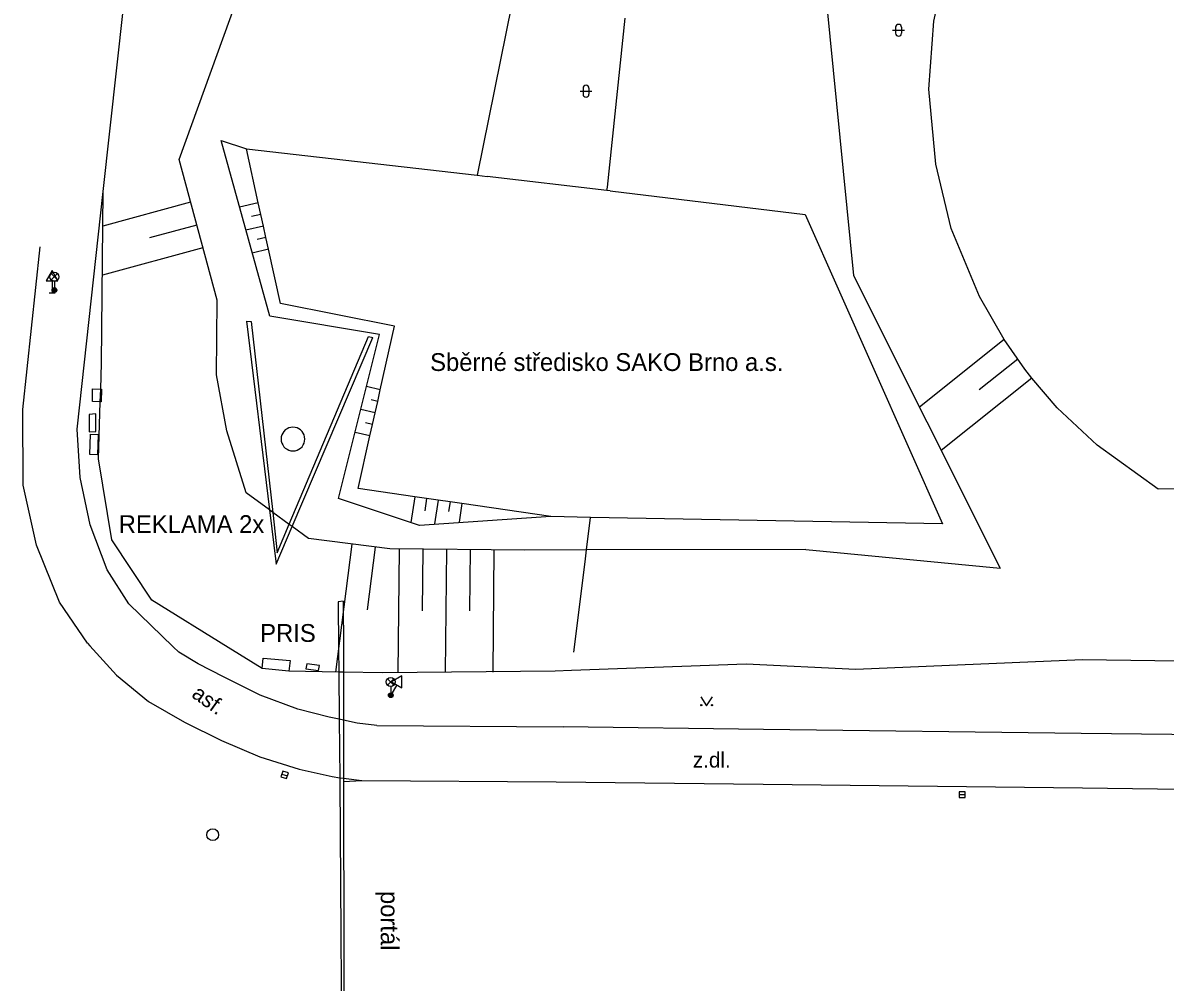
# Model space of a CAD drawing. Extents: x -602419 to -601554, y -1162937 to -1162362.
# Drawn here: x -602032.16 to -601984.03, y -1162718.74 to -1162678.29 of the extents above; entities that cross this region are included whole.
import ezdxf

# ---------------------------------------------------------------- set-up
doc = ezdxf.new("R2010")
doc.units = 0
doc.layers.add('Podklad', color=7, linetype='Continuous')

msp = doc.modelspace()

# ---------------------------------------------------------------- linework, layer by layer
at = {"layer": 'Podklad'}
for p, q in [((-601995.513, -1162678.608), (-601995.013, -1162678.608)), ((-601995.388, -1162678.483), (-601995.388, -1162678.733)), ((-601995.138, -1162678.483), (-601995.138, -1162678.733)), ((-602008.683, -1162681.178), (-602008.183, -1162681.178)), ((-602008.558, -1162681.053), (-602008.558, -1162681.303)), ((-602008.308, -1162681.053), (-602008.308, -1162681.303)), ((-602032.1599, -1162694.59), (-602031.43, -1162687.73)), ((-602030.9625, -1162689.13), (-602030.6975, -1162688.865)), ((-602030.9625, -1162688.865), (-602030.6975, -1162689.13)), ((-602030.93, -1162689.171), (-602030.93, -1162689.68)), ((-602030.83, -1162689.185), (-602030.83, -1162689.56)), ((-602031.055, -1162689.68), (-602030.805, -1162689.68)), ((-602016.7925, -1162706.21), (-602016.5275, -1162705.945)), ((-602016.7925, -1162705.945), (-602016.5275, -1162706.21)), ((-602016.4055, -1162706.1992), (-602016.66, -1162706.64)), ((-602016.66, -1162706.265), (-602016.66, -1162706.64)), ((-602016.7683, -1162706.5775), (-602016.5517, -1162706.7025)), ((-602021.2494, -1162709.9629), (-602021.0106, -1162710.0371)), ((-601992.705, -1162710.83), (-601992.455, -1162710.83))]:
    msp.add_line(p, q, dxfattribs=at)
for points in [[(-601928.54, -1162694.32), (-601947.71, -1162697.88), (-601984.32, -1162697.95), (-601986.89, -1162696.1), (-601988.58, -1162694.52), (-601989.65, -1162693.28), (-601989.95, -1162692.89), (-601990.81, -1162691.65), (-601991.85, -1162689.83), (-601993.05, -1162686.96), (-601993.69, -1162684.25), (-601993.99, -1162681.09), (-601993.78, -1162678.2199), (-601988.57, -1162654.98)], [(-602029.87, -1162695.42), (-602028.77, -1162685.4), (-602027.35, -1162672.42)], [(-601998.59, -1162674.46), (-601997.1599, -1162688.95), (-601990.98, -1162701.28)], [(-602021.77, -1162698.83), (-602022.75, -1162698.11), (-602023.56, -1162695.49), (-602024, -1162693.13), (-602023.97, -1162689.98), (-602025.58, -1162684.06), (-602022.9, -1162676.66)], [(-602011.56, -1162677.49), (-602013.02, -1162684.72)], [(-602007.5488, -1162685.3648), (-602007.533, -1162685.2149), (-602006.7841, -1162678.0983)], [(-602009.92, -1162699.11), (-602015.45, -1162699.48), (-602018.86, -1162698.34), (-602017.13, -1162691.43), (-602021.76, -1162690.66), (-602023.8, -1162683.26), (-602022.74, -1162683.61)], [(-602007.42, -1162685.38), (-601999.2, -1162686.37), (-601993.4099, -1162699.42), (-602008.24, -1162699.14), (-602009.92, -1162699.11), (-602013.67, -1162698.56), (-602015.15, -1162698.34), (-602015.65, -1162698.27), (-602018.03, -1162697.92), (-602017.54, -1162695.71), (-602017.43, -1162695.23), (-602017.32, -1162694.74), (-602017.21, -1162694.25), (-602017.1, -1162693.77), (-602016.5, -1162691.08), (-602021.3, -1162690.13), (-602021.81, -1162687.83), (-602021.92, -1162687.34), (-602022.02, -1162686.86), (-602022.13, -1162686.37), (-602022.24, -1162685.88), (-602022.74, -1162683.61), (-602013.02, -1162684.72), (-602012.59, -1162684.77)], [(-602007.42, -1162685.38), (-602007.5488, -1162685.3648), (-602012.59, -1162684.77)], [(-602028.88, -1162693.73), (-602028.85, -1162692.64), (-602028.77, -1162685.4)], [(-602025.09, -1162685.85), (-602028.79, -1162686.86)], [(-602022.24, -1162685.88), (-602023.03, -1162686.07)], [(-602022.13, -1162686.37), (-602022.53, -1162686.46)], [(-602024.83, -1162686.82), (-602026.82, -1162687.36)], [(-602022.02, -1162686.86), (-602022.76, -1162687.03)], [(-602021.92, -1162687.34), (-602022.29, -1162687.43)], [(-602024.57, -1162687.78), (-602028.81, -1162688.93)], [(-602021.81, -1162687.83), (-602022.5, -1162688)], [(-602022.74, -1162690.87), (-602021.77, -1162698.83)], [(-602022.74, -1162690.87), (-602022.54, -1162690.88), (-602021.63, -1162698.93)], [(-602020.94, -1162699.43), (-602017.6, -1162691.52), (-602017.41, -1162691.56)], [(-602020.81, -1162699.53), (-602017.41, -1162691.56)], [(-601990.81, -1162691.65), (-601994.38, -1162694.49)], [(-601990.24, -1162692.4699), (-601991.87, -1162693.76)], [(-601989.65, -1162693.28), (-601993.4699, -1162696.32)], [(-602029.23, -1162694.26), (-602029.22, -1162693.72)], [(-602029.22, -1162693.72), (-602028.88, -1162693.73)], [(-602028.9, -1162694.27), (-602028.88, -1162693.73)], [(-602028.88, -1162693.73), (-602028.85, -1162693.73)], [(-602028.85, -1162693.73), (-602028.86, -1162694.27)], [(-602017.1, -1162693.77), (-602017.68, -1162693.63)], [(-602028.9, -1162694.27), (-602029.23, -1162694.26)], [(-602022.07, -1162705.51), (-602023.5025, -1162704.6228), (-602026.72, -1162702.63), (-602028.41, -1162700.09), (-602028.97, -1162696.67), (-602028.9, -1162694.27)], [(-602022.07, -1162705.51), (-602023.5025, -1162704.6228), (-602026.72, -1162702.63), (-602028.41, -1162700.09), (-602028.97, -1162696.67), (-602028.9, -1162694.27)], [(-602028.86, -1162694.27), (-602028.9, -1162694.27)], [(-602017.21, -1162694.25), (-602017.48, -1162694.19)], [(-602030.62, -1162702.71), (-602031.59, -1162700.31), (-602032.14, -1162697.78), (-602032.1599, -1162694.59)], [(-602017.32, -1162694.74), (-602017.92, -1162694.6)], [(-602029.08, -1162694.78), (-602029.36, -1162694.8)], [(-602029.36, -1162694.8), (-602029.36, -1162695.54)], [(-602029.08, -1162695.52), (-602029.08, -1162694.78)], [(-602017.43, -1162695.23), (-602017.72, -1162695.16)], [(-602029.74, -1162697.46), (-602029.87, -1162695.42)], [(-602029.36, -1162695.54), (-602029.08, -1162695.52)], [(-602029.34, -1162696.49), (-602029.31, -1162695.64)], [(-602029.31, -1162695.64), (-602028.98, -1162695.65)], [(-602028.98, -1162695.65), (-602029.02, -1162696.5)], [(-602020.28, -1162695.84), (-602020.2876, -1162695.7532), (-602020.3102, -1162695.669), (-602020.347, -1162695.59), (-602020.397, -1162695.5186), (-602020.4586, -1162695.457), (-602020.53, -1162695.407), (-602020.609, -1162695.3702), (-602020.6932, -1162695.3476), (-602020.78, -1162695.34), (-602020.8668, -1162695.3476), (-602020.951, -1162695.3702), (-602021.03, -1162695.407), (-602021.1014, -1162695.457), (-602021.163, -1162695.5186), (-602021.213, -1162695.59), (-602021.2498, -1162695.669), (-602021.2724, -1162695.7532), (-602021.28, -1162695.84), (-602021.2724, -1162695.9268), (-602021.2498, -1162696.011), (-602021.213, -1162696.09), (-602021.163, -1162696.1614), (-602021.1014, -1162696.223), (-602021.03, -1162696.273), (-602020.951, -1162696.3098), (-602020.8668, -1162696.3324), (-602020.78, -1162696.34), (-602020.6932, -1162696.3324), (-602020.609, -1162696.3098), (-602020.53, -1162696.273), (-602020.4586, -1162696.223), (-602020.397, -1162696.1614), (-602020.347, -1162696.09), (-602020.3102, -1162696.011), (-602020.2876, -1162695.9268), (-602020.28, -1162695.84)], [(-602017.54, -1162695.71), (-602018.16, -1162695.57)], [(-602029.02, -1162696.5), (-602029.34, -1162696.49)], [(-602028.61, -1162701.36), (-602029.32, -1162699.45), (-602029.74, -1162697.46)], [(-602015.65, -1162698.27), (-602015.81, -1162699.36)], [(-602015.15, -1162698.34), (-602015.23, -1162698.86)], [(-602014.66, -1162698.41), (-602014.81, -1162699.42)], [(-602014.16, -1162698.49), (-602014.22, -1162698.89)], [(-602013.67, -1162698.56), (-602013.78, -1162699.34)], [(-602021.77, -1162698.83), (-602021.49, -1162701.11)], [(-602021.63, -1162698.93), (-602021.77, -1162698.83)], [(-602020.94, -1162699.44), (-602021.63, -1162698.93)], [(-602021.63, -1162698.93), (-602021.44, -1162700.63), (-602020.94, -1162699.43)], [(-602021.49, -1162701.11), (-602020.81, -1162699.53)], [(-602020.81, -1162699.53), (-602020.94, -1162699.44)], [(-602008.41, -1162700.51), (-602011.01, -1162700.52), (-602016.7, -1162700.47), (-602020.12, -1162700.03), (-602020.81, -1162699.53)], [(-602008.41, -1162700.51), (-602008.24, -1162699.14)], [(-602018.3, -1162700.27), (-602018.99, -1162705.66)], [(-602018.3, -1162700.27), (-602018.99, -1162705.66)], [(-602017.31, -1162700.4), (-602017.65, -1162703.04)], [(-602016.31, -1162700.48), (-602016.36, -1162705.69)], [(-602016.31, -1162700.48), (-602016.36, -1162705.69)], [(-602015.31, -1162700.48), (-602015.34, -1162703.08)], [(-602014.31, -1162700.49), (-602014.36, -1162705.67)], [(-602014.31, -1162700.49), (-602014.36, -1162705.67)], [(-602013.31, -1162700.5), (-602013.34, -1162703.08)], [(-602012.31, -1162700.51), (-602012.36, -1162705.66)], [(-602012.31, -1162700.51), (-602012.36, -1162705.66)], [(-602008.949, -1162704.826), (-602008.4738, -1162701.0129), (-602008.41, -1162700.51)], [(-602008.949, -1162704.826), (-602008.4738, -1162701.0129), (-602008.41, -1162700.51)], [(-601999.17, -1162700.49), (-602008.41, -1162700.51)], [(-601999.17, -1162700.49), (-601990.98, -1162701.28)], [(-602025.59, -1162704.83), (-602025.8276, -1162704.5981), (-602027.69, -1162702.78), (-602028.61, -1162701.36)], [(-602025.59, -1162704.83), (-602025.8276, -1162704.5981), (-602027.69, -1162702.78), (-602028.61, -1162701.36)], [(-602029.44, -1162704.45), (-602030.62, -1162702.71)], [(-602018.66, -1162702.68), (-602018.87, -1162702.7), (-602018.8567, -1162704.6776), (-602018.85, -1162705.67)], [(-602018.66, -1162702.68), (-602018.87, -1162702.7), (-602018.8567, -1162704.6776), (-602018.85, -1162705.67)], [(-602018.66, -1162702.68), (-602018.6533, -1162704.6805), (-602018.65, -1162705.67)], [(-602018.66, -1162702.68), (-602018.6533, -1162704.6805), (-602018.65, -1162705.67)], [(-602029.44, -1162704.45), (-602029.337, -1162704.5631), (-602028.21, -1162705.8), (-602026.86, -1162706.9), (-602025.35, -1162707.77), (-602023.79, -1162708.55), (-602022.18, -1162709.23), (-602020.52, -1162709.75), (-602019.13, -1162710.07), (-602018.81, -1162710.12)], [(-602029.44, -1162704.45), (-602029.337, -1162704.5631), (-602028.21, -1162705.8), (-602026.86, -1162706.9), (-602025.35, -1162707.77), (-602023.79, -1162708.55), (-602022.18, -1162709.23), (-602020.52, -1162709.75), (-602019.13, -1162710.07), (-602018.81, -1162710.12)], [(-602018.83, -1162707.65), (-602019.26, -1162707.57), (-602020.57, -1162707.2199), (-602022.1599, -1162706.63), (-602023.7, -1162705.86), (-602024.78, -1162705.32), (-602025.59, -1162704.83)], [(-602022.07, -1162705.51), (-602022.03, -1162705.07)], [(-602022.03, -1162705.07), (-602020.9, -1162705.18)], [(-602020.9, -1162705.18), (-602020.95, -1162705.62)], [(-602020.2, -1162705.31), (-602020.24, -1162705.52)], [(-602019.66, -1162705.38), (-602020.2, -1162705.31)], [(-602001.68, -1162705.33), (-602009.05, -1162705.6), (-602009.73, -1162705.63), (-602017.01, -1162705.7), (-602018.65, -1162705.67)], [(-601997.07, -1162705.56), (-602001.68, -1162705.33)], [(-601987.51, -1162705.15), (-601997.07, -1162705.56)], [(-601987.51, -1162705.15), (-601997.07, -1162705.56)], [(-601984.4699, -1162705.19), (-601987.51, -1162705.15)], [(-601984.4699, -1162705.19), (-601987.51, -1162705.15)], [(-601944.44, -1162705.77), (-601984.4699, -1162705.19)], [(-601944.44, -1162705.77), (-601984.4699, -1162705.19)], [(-602020.95, -1162705.62), (-602022.07, -1162705.51)], [(-602018.85, -1162705.67), (-602020.95, -1162705.62)], [(-602020.24, -1162705.52), (-602019.7, -1162705.59)], [(-602019.7, -1162705.59), (-602019.66, -1162705.38)], [(-602018.65, -1162705.67), (-602018.85, -1162705.67)], [(-602018.85, -1162705.67), (-602018.83, -1162707.65)], [(-602018.65, -1162705.67), (-602018.65, -1162707.69)], [(-602003.6, -1162706.705), (-602003.35, -1162707.08), (-602003.1, -1162706.705)], [(-602018.65, -1162707.69), (-602018.83, -1162707.65)], [(-602018.83, -1162707.65), (-602018.81, -1162710.12)], [(-602017.24, -1162707.9099), (-602018.07, -1162707.81), (-602018.65, -1162707.69)], [(-602018.65, -1162707.69), (-602018.65, -1162710.14)], [(-602017.24, -1162707.9099), (-602009.39, -1162707.9699)], [(-602000.95, -1162708.09), (-602009.39, -1162707.9699)], [(-601947.1599, -1162708.6), (-601950.25, -1162708.6), (-601962.68, -1162708.49), (-601974.84, -1162708.39), (-601987.57, -1162708.25), (-602000.95, -1162708.09)], [(-602018.81, -1162710.12), (-602018.65, -1162710.14)], [(-602018.81, -1162710.12), (-602018.81, -1162710.28)], [(-602018.65, -1162710.14), (-602017.88, -1162710.24)], [(-602018.65, -1162710.14), (-602018.65, -1162710.27)], [(-602018.81, -1162710.28), (-602018.7, -1162725.26)], [(-602018.65, -1162710.27), (-602017.88, -1162710.24)], [(-602018.65, -1162710.27), (-602018.62, -1162725.26)], [(-602017.88, -1162710.24), (-602009.69, -1162710.29), (-602000.9699, -1162710.39)], [(-602000.9699, -1162710.39), (-601987.51, -1162710.55), (-601974.87, -1162710.71), (-601962.68, -1162710.81), (-601950.23, -1162710.9099), (-601939.26, -1162710.95)]]:
    msp.add_lwpolyline(points, dxfattribs=at)
for points in [[(-602031.18, -1162689.171), (-602030.68, -1162689.171), (-602030.93, -1162688.738)], [(-602016.622, -1162706.0742), (-602016.189, -1162706.3242), (-602016.189, -1162705.8242)], [(-602021.2865, -1162710.0823), (-602021.0477, -1162710.1565), (-602020.9735, -1162709.9177), (-602021.2123, -1162709.8435)], [(-601992.705, -1162710.955), (-601992.455, -1162710.955), (-601992.455, -1162710.705), (-601992.705, -1162710.705)]]:
    msp.add_lwpolyline(points, close=True, dxfattribs=at)
for centre, radius in [((-602030.83, -1162688.9975), 0.1875), ((-602030.83, -1162689.56), 0.1), ((-602030.83, -1162689.56), 0.0723), ((-602030.83, -1162689.56), 0.0438), ((-602016.66, -1162706.0775), 0.1875), ((-602016.66, -1162706.64), 0.1), ((-602016.66, -1162706.64), 0.0723), ((-602016.66, -1162706.64), 0.0438), ((-602003.5751, -1162707.0549), 0.025), ((-602003.1254, -1162707.0549), 0.025), ((-602024.1599, -1162712.52), 0.25)]:
    msp.add_circle(centre, radius, dxfattribs=at)
for centre, start, end in [((-601995.2629, -1162678.4831), 0, 180), ((-601995.2629, -1162678.7331), 180, 0), ((-602008.4328, -1162681.0531), 0, 180), ((-602008.4328, -1162681.3031), 180, 0)]:
    msp.add_arc(centre, 0.125, start, end, dxfattribs=at)

# ---------------------------------------------------------------- texts
for s, height, p in [('Sběrné středisko SAKO Brno a.s.', 0.75, (-602015, -1162692.97)), ('REKLAMA 2x', 0.75, (-602028.12, -1162699.8)), ('PRIS', 0.75, (-602022.1599, -1162704.39)), ('z.dl.', 0.65, (-602003.93, -1162709.69))]:
    msp.add_text(s, height=height, dxfattribs=at).set_placement(p)
for s, height, rotation, p in [('asf.', 0.65, 324.47, (-602025.09, -1162706.69)), ('portál', 0.75, 270, (-602017.08, -1162714.89))]:
    msp.add_text(s, height=height, rotation=rotation, dxfattribs=at).set_placement(p)

doc.saveas('drawing.dxf')
